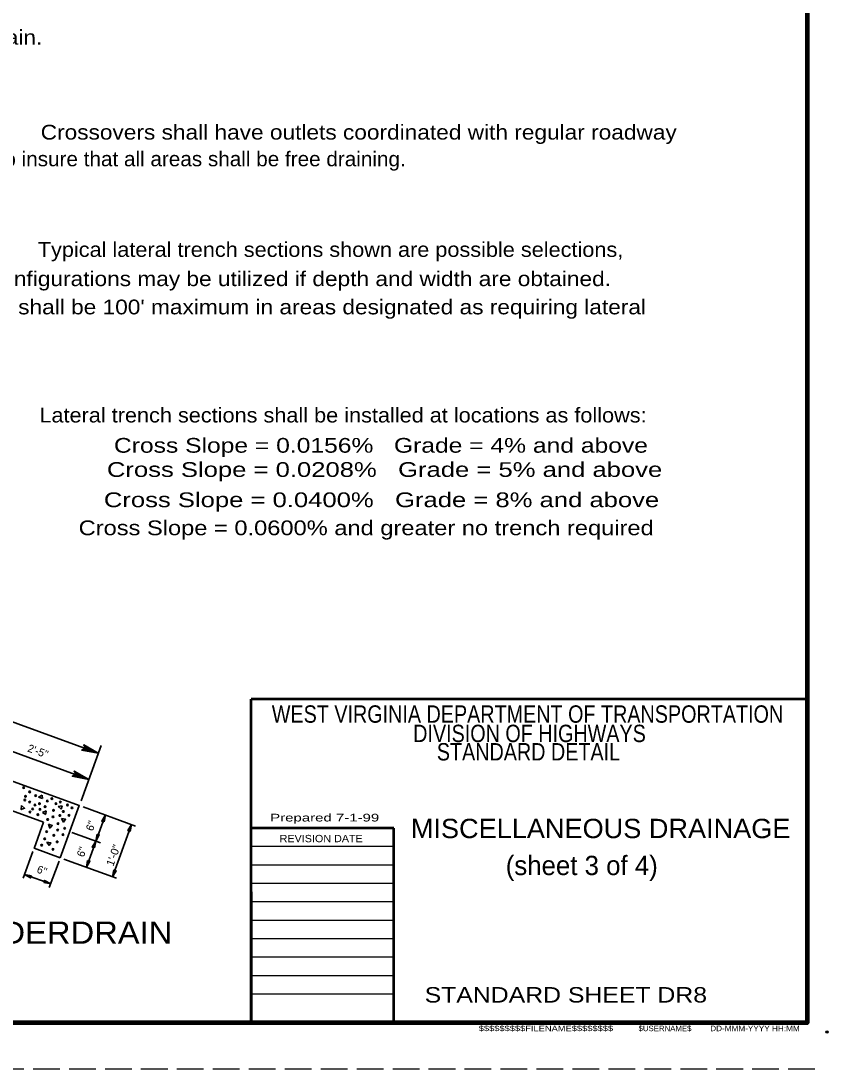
# Model space of a CAD drawing. Extents: x -48732 to -48696.6, y -117659.8 to -117637.8.
# Drawn here: x -48705.33 to -48696.62, y -117659.85 to -117648.54 of the extents above; entities that cross this region are included whole.
import ezdxf
from ezdxf.enums import TextEntityAlignment as Align

# ---------------------------------------------------------------- set-up
doc = ezdxf.new("R2010")
doc.units = 0
doc.header["$LTSCALE"] = 0.048
doc.header["$PDMODE"] = 32
doc.header["$PDSIZE"] = 0.024
doc.linetypes.add('LONG_DASHED', pattern=[7.5, 6, -1.5])
doc.layers.add('1', color=7, linetype='Continuous', lineweight=25)
doc.layers.add('3', color=7, linetype='Continuous', lineweight=35)

msp = doc.modelspace()

# ---------------------------------------------------------------- linework, layer by layer
at = {"layer": '1', "lineweight": 53}
for p, q in [((-48696.84825, -117655.85833), (-48702.84825, -117655.85833)), ((-48702.84825, -117659.34817), (-48702.84825, -117655.85833)), ((-48696.84825, -117659.34817), (-48696.84825, -117656.84917)), ((-48701.31033, -117657.24917), (-48702.84825, -117657.24917)), ((-48701.31033, -117659.34817), (-48701.31033, -117657.24917)), ((-48702.84825, -117657.93817), (-48702.84825, -117659.34817)), ((-48696.84825, -117659.34817), (-48702.84825, -117659.34817))]:
    msp.add_line(p, q, dxfattribs=at)
at = {"layer": '1'}
for p, q in [((-48701.31033, -117657.44917), (-48702.84825, -117657.44917)), ((-48701.31033, -117657.64817), (-48702.84825, -117657.64817)), ((-48701.31033, -117657.84717), (-48702.84825, -117657.84717)), ((-48701.31033, -117658.04617), (-48702.84825, -117658.04617)), ((-48701.31033, -117658.24517), (-48702.84825, -117658.24517)), ((-48701.31033, -117658.44417), (-48702.84825, -117658.44417)), ((-48701.31033, -117658.64317), (-48702.84825, -117658.64317)), ((-48701.31033, -117658.84217), (-48702.84825, -117658.84217)), ((-48701.31033, -117659.04117), (-48702.84825, -117659.04117))]:
    msp.add_line(p, q, dxfattribs=at)
at = {"layer": '1', "linetype": 'LONG_DASHED'}
msp.add_line((-48696.76492, -117659.84817), (-48731.96492, -117659.84817), dxfattribs=at)
at = {"layer": '1', "lineweight": 158}
msp.add_lwpolyline([(-48696.84825, -117638.34817), (-48696.84825, -117659.34817), (-48729.34825, -117659.34817)], dxfattribs=at)
at = {"layer": '1'}
for p in [(-48696.84825, -117659.34817), (-48696.63525, -117659.44817)]:
    msp.add_point(p, dxfattribs=at)
at = {"layer": '3'}
for p, q in [((-48706.8485, -117655.587), (-48704.4975, -117656.442)), ((-48704.4675, -117656.359), (-48704.6835, -117656.955)), ((-48706.0585, -117656.833), (-48705.0875, -117657.186)), ((-48705.1035, -117656.894), (-48705.1415, -117656.915)), ((-48705.1415, -117656.915), (-48705.1005, -117656.932)), ((-48705.1005, -117656.93), (-48705.1035, -117656.894)), ((-48704.8885, -117657.009), (-48704.9315, -117657.016)), ((-48704.9315, -117657.016), (-48704.8985, -117657.046)), ((-48704.8975, -117657.044), (-48704.8885, -117657.009)), ((-48704.6625, -117657.021), (-48704.0965, -117657.228)), ((-48705.0595, -117657.065), (-48705.1005, -117657.08)), ((-48705.1005, -117657.08), (-48705.0625, -117657.103)), ((-48705.0625, -117657.101), (-48705.0595, -117657.065)), ((-48704.4215, -117657.108), (-48704.6265, -117657.672)), ((-48705.0875, -117657.186), (-48705.1905, -117657.468)), ((-48704.1395, -117657.211), (-48704.3445, -117657.775)), ((-48704.7825, -117657.297), (-48704.4735, -117657.408)), ((-48705.1905, -117657.467), (-48704.9085, -117657.57)), ((-48705.0295, -117657.439), (-48705.0525, -117657.401)), ((-48705.2035, -117657.502), (-48705.3085, -117657.789)), ((-48704.9215, -117657.605), (-48705.0265, -117657.892)), ((-48704.8685, -117657.584), (-48704.3025, -117657.791)), ((-48705.2935, -117657.749), (-48705.0115, -117657.852))]:
    msp.add_line(p, q, dxfattribs=at)
for points in [[(-48708.4625, -117655.638), (-48704.7035, -117657.006), (-48704.9085, -117657.57)], [(-48706.9505, -117655.869), (-48705.7725, -117656.297), (-48704.6005, -117656.724)], [(-48704.6765, -117656.408), (-48704.4975, -117656.442), (-48704.6545, -117656.352), (-48704.6535, -117656.357), (-48704.5145, -117656.435), (-48704.6715, -117656.406), (-48704.6655, -117656.404), (-48704.5315, -117656.429), (-48704.6495, -117656.362), (-48704.6465, -117656.367), (-48704.5485, -117656.422), (-48704.6605, -117656.403), (-48704.6545, -117656.4), (-48704.5655, -117656.416), (-48704.6435, -117656.371), (-48704.6405, -117656.377), (-48704.5815, -117656.41), (-48704.6475, -117656.399), (-48704.6425, -117656.395), (-48704.5975, -117656.405), (-48704.6375, -117656.382), (-48704.6355, -117656.388), (-48704.6155, -117656.397), (-48704.6365, -117656.395), (-48704.6765, -117656.408), (-48704.6315, -117656.391), (-48704.6545, -117656.352)], [(-48704.7795, -117656.69), (-48704.6005, -117656.724), (-48704.7575, -117656.634), (-48704.7565, -117656.639), (-48704.6175, -117656.717), (-48704.7745, -117656.688), (-48704.7685, -117656.686), (-48704.6345, -117656.711), (-48704.7525, -117656.644), (-48704.7495, -117656.649), (-48704.6515, -117656.704), (-48704.7635, -117656.685), (-48704.7575, -117656.682), (-48704.6685, -117656.698), (-48704.7465, -117656.653), (-48704.7435, -117656.659), (-48704.6845, -117656.692), (-48704.7505, -117656.681), (-48704.7455, -117656.677), (-48704.7005, -117656.687), (-48704.7405, -117656.664), (-48704.7385, -117656.67), (-48704.7185, -117656.679), (-48704.7395, -117656.677), (-48704.7795, -117656.69), (-48704.7345, -117656.673), (-48704.7575, -117656.634)], [(-48705.0295, -117657.439), (-48705.0095, -117657.409), (-48705.0525, -117657.401)]]:
    msp.add_lwpolyline(points, dxfattribs=at)
for points in [[(-48705.3275, -117657.006), (-48705.3285, -117657.05), (-48705.2935, -117657.035)], [(-48704.8945, -117657.146), (-48704.8735, -117657.184), (-48704.8505, -117657.154)], [(-48704.4355, -117657.182), (-48704.4595, -117657.174), (-48704.4215, -117657.108)], [(-48705.0355, -117657.206), (-48705.0215, -117657.249), (-48704.9945, -117657.222)], [(-48704.1535, -117657.285), (-48704.1775, -117657.277), (-48704.1395, -117657.211)], [(-48704.5105, -117657.316), (-48704.4865, -117657.324), (-48704.5245, -117657.39)], [(-48704.5385, -117657.464), (-48704.5625, -117657.456), (-48704.5245, -117657.39)], [(-48704.6125, -117657.598), (-48704.5885, -117657.606), (-48704.6265, -117657.672)], [(-48704.3305, -117657.701), (-48704.3065, -117657.709), (-48704.3445, -117657.775)], [(-48705.2195, -117657.763), (-48705.2275, -117657.787), (-48705.2935, -117657.749)], [(-48705.0855, -117657.838), (-48705.0775, -117657.814), (-48705.0115, -117657.852)]]:
    msp.add_lwpolyline(points, close=True, dxfattribs=at)
for centre in [(-48705.3025, -117656.813), (-48705.2835, -117656.908), (-48705.2385, -117656.859), (-48705.1735, -117656.9), (-48704.9985, -117656.931), (-48705.2905, -117656.947), (-48705.2385, -117656.969), (-48705.2065, -117657.043), (-48705.1805, -117657), (-48705.1325, -117656.986), (-48705.1265, -117657.047), (-48705.0715, -117657.018), (-48705.0475, -117656.957), (-48704.9535, -117656.986), (-48704.9065, -117656.969), (-48704.8295, -117657), (-48704.7825, -117657.031), (-48705.2355, -117657.076), (-48705.1495, -117657.104), (-48705.0435, -117657.157), (-48704.9855, -117657.128), (-48704.9815, -117657.059), (-48704.9125, -117657.114), (-48704.8755, -117657.071), (-48704.8145, -117657.112), (-48704.9365, -117657.271), (-48704.9325, -117657.202), (-48704.8595, -117657.251), (-48705.0755, -117657.365), (-48705.0555, -117657.288), (-48704.9775, -117657.328), (-48704.8795, -117657.32), (-48705.1085, -117657.434), (-48704.9855, -117657.479), (-48704.9415, -117657.398)]:
    msp.add_circle(centre, 0.00848, dxfattribs=at)

# ---------------------------------------------------------------- texts
at = {"layer": '1'}
for s, height, width, p in [(' edge drain.', 0.159, 1.15, (-48706.39358, -117648.80025)), ('Crossovers shall have outlets coordinated with regular roadway', 0.159, 1.15, (-48705.11917, -117649.82342)), ('outlets to insure that all areas shall be free draining.', 0.159, 1.05, (-48706.29308, -117650.11158)), ('Typical lateral trench sections shown are possible selections, ', 0.159, 1.1, (-48705.15067, -117651.08883)), ('Typical lateral trench sections shown are possible selections, ', 0.159, 1.1, (-48705.15067, -117651.08883)), ('other configurations may be utilized if depth and width are obtained.', 0.159, 1.15, (-48706.29192, -117651.40417)), ("Spacing shall be 100' maximum in areas designated as requiring lateral", 0.159, 1.15, (-48706.31367, -117651.70867)), ('Lateral trench sections shall be installed at locations as follows:', 0.159, 1.1, (-48705.13317, -117652.87475)), ('Cross Slope = 0.0156%   Grade = 4% and above', 0.159, 1.25, (-48704.32883, -117653.201)), ('Cross Slope = 0.0208%   Grade = 5% and above', 0.159, 1.3, (-48704.40492, -117653.46192)), ('Cross Slope = 0.0400%   Grade = 8% and above', 0.159, 1.3, (-48704.43767, -117653.78817)), ('Cross Slope = 0.0600% and greater no trench required', 0.159, 1.2, (-48704.70967, -117654.09067)), ('REVISION DATE', 0.079, 1.1, (-48702.54117, -117657.40183)), ('$$$$$$$$$FILENAME$$$$$$$$', 0.06, 1.25, (-48700.3925, -117659.43992)), ('$USERNAME$', 0.06, 1.05, (-48698.66842, -117659.43992)), ('DD-MMM-YYYY HH:MM', 0.06, 1.1, (-48697.89483, -117659.43992))]:
    msp.add_text(s, height=height, dxfattribs=dict(at, width=width)).set_placement(p)
for s, height, width, p in [('WEST VIRGINIA DEPARTMENT OF TRANSPORTATION', 0.1875, 0.85, (-48699.86646, -117656.11325)), ('DIVISION OF HIGHWAYS', 0.1875, 0.85, (-48699.84458, -117656.32217)), ('STANDARD DETAIL', 0.1875, 0.85, (-48699.85588, -117656.52033)), ('  Prepared 7-1-99 ', 0.08333, 1.45, (-48702.07708, -117657.17825)), (' MISCELLANEOUS DRAINAGE ', 0.2083, 1.05, (-48699.077, -117657.35767)), ('STANDARD SHEET DR8         ', 0.1667, 1.2, (-48699.11804, -117659.13108))]:
    msp.add_text(s, height=height, dxfattribs=dict(at, width=width)).set_placement(p, align=Align.CENTER)
msp.add_text(' (sheet 3 of 4)', height=0.2083, dxfattribs=at).set_placement((-48699.31954, -117657.75642), align=Align.CENTER)
at = {"layer": '3'}
for s, rotation, p in [("2'-5''", 340.033, (-48705.2685, -117656.421)), ("6''", 70.017, (-48704.5565, -117657.288)), ("6''", 70.017, (-48704.6545, -117657.569)), ("6''", 340.017, (-48705.1685, -117657.727))]:
    msp.add_text(s, height=0.084, rotation=rotation, dxfattribs=at).set_placement(p)
at = {"layer": '3', "width": 1.05}
msp.add_text('1\'-0"', height=0.084, rotation=70.017, dxfattribs=at).set_placement((-48704.3365, -117657.668))
at = {"layer": '3', "width": 1.1}
msp.add_text('SLOPEWALL FOR UNDERDRAIN', height=0.24, dxfattribs=at).set_placement((-48709.1325, -117658.497))

doc.saveas('drawing.dxf')
